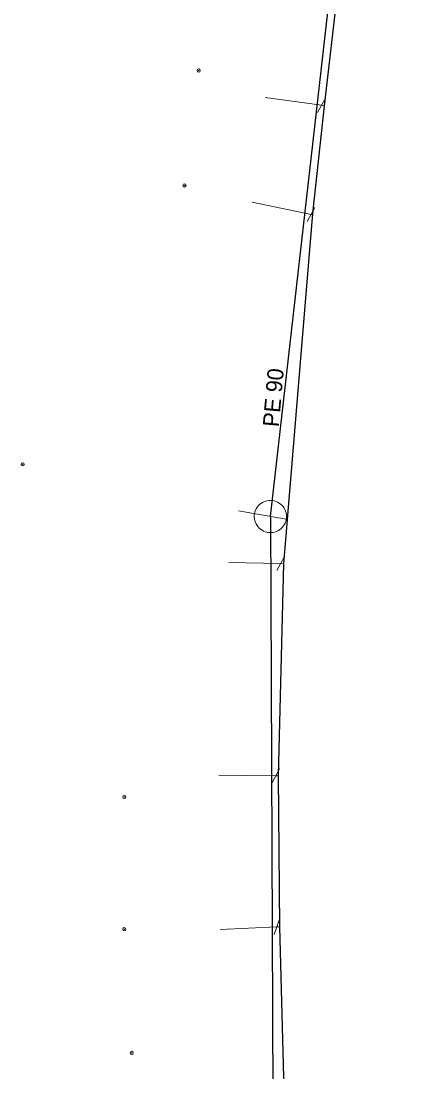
# Model space of a CAD drawing. Extents: x -783064 to -782702, y -1007904 to -1007145.
# Drawn here: x -782955.2 to -782930.9, y -1007512.4 to -1007447.1 of the extents above; entities that cross this region are included whole.
import ezdxf

# ---------------------------------------------------------------- set-up
doc = ezdxf.new("R2010")
doc.units = 0
doc.header["$LTSCALE"] = 0.4
doc.header["$PDMODE"] = 32
doc.header["$PDSIZE"] = 0.2
for name, color, linetype, lineweight in [('1', 7, 'Continuous', 13), ('13', 7, 'Continuous', 13), ('14', 7, 'Continuous', 13), ('17', 7, 'Continuous', 25), ('22', 7, 'Continuous', 13), ('34', 7, 'Continuous', 13)]:
    doc.layers.add(name, color=color, linetype=linetype, lineweight=lineweight)

msp = doc.modelspace()

# ---------------------------------------------------------------- linework, layer by layer
at = {"layer": '1'}
for p in [(-782944.19, -1007450.199), (-782945.07, -1007457.339), (-782955.12, -1007474.679), (-782948.809, -1007495.349), (-782948.809, -1007503.569), (-782948.35, -1007511.259)]:
    msp.add_point(p, dxfattribs=at)
at = {"layer": '13'}
for p, q in [((-782936.566, -1007452.36), (-782940.07, -1007451.868)), ((-782937.216, -1007459.149), (-782940.866, -1007458.386)), ((-782939.095, -1007480.839), (-782942.324, -1007480.769)), ((-782939.417, -1007494.046), (-782942.943, -1007493.993)), ((-782939.34, -1007503.421), (-782942.852, -1007503.583))]:
    msp.add_line(p, q, dxfattribs=at)
at = {"layer": '14', "lineweight": 25}
for q in [(-782930.949, -1007400.43), (-782939.43, -1007554.87)]:
    msp.add_line((-782939.739, -1007477.92), q, dxfattribs=at)
at = {"layer": '14'}
for p, q in [((-782936.401, -1007452.394), (-782936.566, -1007452.36)), ((-782937.129, -1007459.088), (-782937.216, -1007459.149)), ((-782938.934, -1007480.861), (-782939.095, -1007480.839)), ((-782939.259, -1007494.042), (-782939.417, -1007494.046)), ((-782939.179, -1007503.419), (-782939.34, -1007503.421))]:
    msp.add_line(p, q, dxfattribs=at)
at = {"layer": '17'}
msp.add_lwpolyline([(-782931.92, -1007401.104), (-782931.956, -1007401.549), (-782932.488, -1007408.389), (-782933.956, -1007428.826), (-782935.107, -1007441.291), (-782936.401, -1007452.394), (-782937.129, -1007459.088), (-782938.934, -1007480.861), (-782939.259, -1007494.042), (-782939.179, -1007503.419), (-782938.89, -1007514.33), (-782939.048, -1007525.032), (-782938.934, -1007539.638), (-782938.382, -1007552.936)], dxfattribs=at)
at = {"layer": '22'}
msp.add_line((-782941.709, -1007477.572), (-782938.754, -1007478.093), dxfattribs=at)
msp.add_lwpolyline([(-782939.913, -1007478.904), (-782939.804, -1007478.917), (-782939.695, -1007478.918), (-782939.585, -1007478.907), (-782939.479, -1007478.885), (-782939.374, -1007478.851), (-782939.275, -1007478.805), (-782939.181, -1007478.749), (-782939.094, -1007478.683), (-782939.014, -1007478.608), (-782938.943, -1007478.525), (-782938.881, -1007478.434), (-782938.831, -1007478.336), (-782938.79, -1007478.235), (-782938.762, -1007478.129), (-782938.744, -1007478.021), (-782938.739, -1007477.912), (-782938.746, -1007477.802), (-782938.764, -1007477.694), (-782938.795, -1007477.589), (-782938.836, -1007477.489), (-782938.889, -1007477.392), (-782938.952, -1007477.303), (-782939.025, -1007477.22), (-782939.105, -1007477.146), (-782939.193, -1007477.081), (-782939.288, -1007477.027), (-782939.389, -1007476.983), (-782939.493, -1007476.95), (-782939.601, -1007476.929), (-782939.71, -1007476.92), (-782939.819, -1007476.922), (-782939.927, -1007476.938), (-782940.034, -1007476.964), (-782940.137, -1007477.001), (-782940.235, -1007477.051), (-782940.326, -1007477.11), (-782940.412, -1007477.179), (-782940.488, -1007477.257), (-782940.556, -1007477.343), (-782940.614, -1007477.436), (-782940.662, -1007477.534), (-782940.699, -1007477.637), (-782940.724, -1007477.745), (-782940.737, -1007477.853), (-782940.738, -1007477.963), (-782940.727, -1007478.071), (-782940.705, -1007478.179), (-782940.67, -1007478.283), (-782940.625, -1007478.383), (-782940.569, -1007478.477), (-782940.504, -1007478.564), (-782940.428, -1007478.644), (-782940.345, -1007478.715), (-782940.255, -1007478.776), (-782940.158, -1007478.827), (-782940.055, -1007478.868), (-782939.95, -1007478.897)], close=True, dxfattribs=at)
at = {"layer": '34'}
for p, q in [((-782936.327, -1007451.92), (-782936.805, -1007452.798)), ((-782936.977, -1007458.709), (-782937.455, -1007459.587)), ((-782938.856, -1007480.399), (-782939.334, -1007481.277)), ((-782939.178, -1007493.606), (-782939.656, -1007494.484)), ((-782939.179, -1007502.947), (-782939.501, -1007503.894))]:
    msp.add_line(p, q, dxfattribs=at)

# ---------------------------------------------------------------- texts
at = {"layer": '1'}
msp.add_text('PE 90 ', height=1, rotation=85, dxfattribs=at).set_placement((-782939.219, -1007472.383))

doc.saveas('drawing.dxf')
